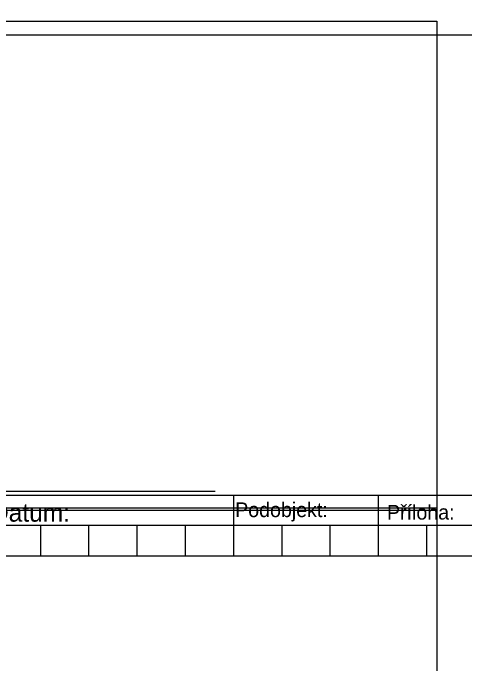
# Model space of a CAD drawing. Extents: x 1391 to 5528, y -6194 to 565.
# Drawn here: x 4185 to 4555, y -1725 to -1193 of the extents above; entities that cross this region are included whole.
import ezdxf

# ---------------------------------------------------------------- set-up
doc = ezdxf.new("R2010")
doc.units = 0
for name, color, linetype in [('Vrstva 11', 7, 'Continuous'), ('Vrstva 2', 7, 'Continuous'), ('Vrstva 3', 7, 'Continuous'), ('Vrstva 8', 7, 'Continuous')]:
    doc.layers.add(name, color=color, linetype=linetype)

# ---------------------------------------------------------------- blocks, each defined once
blk = doc.blocks.new('_U1')
at = {"layer": 'Vrstva 8'}
for p, q in [((3.35, 0.25), (3.35, -0.25)), ((4.535, 0.25), (4.535, -0.25)), ((8.5, 0), (-8.5, 0)), ((1.77, 0), (1.77, -0.25)), ((2.165, 0), (2.165, -0.25)), ((2.56, 0), (2.56, -0.25)), ((2.955, 0), (2.955, -0.25)), ((3.745, 0), (3.745, -0.25)), ((4.14, 0), (4.14, -0.25)), ((4.93, 0), (4.93, -0.25))]:
    blk.add_line(p, q, dxfattribs=at)
blk.add_lwpolyline([(-8.5, 0.25), (8.5, 0.25), (8.5, -0.25), (-8.5, -0.25)], close=True, dxfattribs=at)
for s, p in [('Podobjekt:', (3.3643, 0.0699)), ('Příloha:', (4.6073, 0.0493))]:
    blk.add_text(s, height=0.12, dxfattribs=at).set_placement(p)
blk = doc.blocks.new('_U2')
at = {"layer": 'Vrstva 3'}
blk.add_line((-2.6675, -1.82505), (2.6675, -1.82505), dxfattribs=at)
for s, p in [('Razítko oprávněné osoby:', (-2.5675, 1.92495)), ('Podpis:', (-2.5675, -2.07505)), ('Datum:', (0.8325, -2.07505))]:
    blk.add_text(s, height=0.15, dxfattribs=at).set_placement(p)
blk = doc.blocks.new('_U3')
at = {"layer": 'Vrstva 2'}
blk.add_lwpolyline([(-5.33255, 2.00005), (5.33245, 2.00005), (5.33245, -1.99995), (-5.33255, -1.99995)], close=True, dxfattribs=at)

msp = doc.modelspace()

# ---------------------------------------------------------------- linework, layer by layer
at = {"layer": 'Vrstva 11'}
msp.add_line((1390.73, -1210.73), (5438.99, -1210.73), dxfattribs=at)

# ---------------------------------------------------------------- block references
at = {"layer": 'Vrstva 2', "xscale": 100, "yscale": 100}
for p in [(3998.89, -1399.75), (3998.89, -1797.75)]:
    msp.add_blockref('_U3', p, dxfattribs=at)
at = {"layer": 'Vrstva 3', "xscale": 100, "yscale": 100}
for p in [(4083.89, -1401.5), (4083.89, -1799.5)]:
    msp.add_blockref('_U2', p, dxfattribs=at)
at = {"layer": 'Vrstva 8', "xscale": 100, "yscale": 100}
msp.add_blockref('_U1', (4030.56, -1612.25), dxfattribs=at)

doc.saveas('drawing.dxf')
